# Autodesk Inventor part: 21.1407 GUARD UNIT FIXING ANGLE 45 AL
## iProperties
Created: 2007-01
Part Number: 21.1407 GUARD UNIT FIXING ANGLE 45 AL
Material: Aluminum-6061
Document SubType Name: Modeling
Designer: Andy Moles
Density: 2.71 g/cm^3
Author: Andy Moles
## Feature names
1. Base1
